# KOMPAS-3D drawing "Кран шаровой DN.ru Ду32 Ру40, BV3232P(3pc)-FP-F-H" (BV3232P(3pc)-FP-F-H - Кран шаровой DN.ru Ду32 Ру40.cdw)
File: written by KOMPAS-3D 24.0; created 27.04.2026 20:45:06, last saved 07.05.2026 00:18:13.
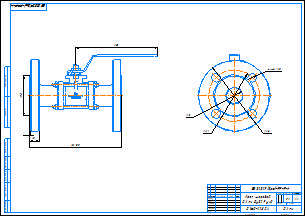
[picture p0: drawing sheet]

Document properties: Автор: Максим; Форматы листов документа: A2; Полное имя файла: BVxxP(3pc)-FP-F-H - Кран шаровой DN.ru Ду32 Ру40.cdw; Масса: 5.095; Наименование: Кран шаровой DN.ru Ду32 Ру40; Количество листов документа: 1; Примечание: D160-22804

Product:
- Body: Тело 1  | qty 1
    Масса: 4.838938
- Part/product: Кран шаровой DN.ru Ду32 Ру40  | designation BV3232P(3pc)-FP-F-H
    Масса: 5.095
    Раздел спецификации: Прочие изделия
    Форматы листов документа: A2
    Примечание: D160-22804

Views: Вид 1, Вид:2, Проекционный вид 2, Вид:1
Referenced files in D:\Rabota ebanaya\Апрель\BVxxP(3pc)-FP-F-H Кран шаровой Ду15-100\Исходники\DN32\: BVxxP(3pc)-FP-F-H - Кран шаровой DN.ru Ду32 Ру40.m3d, BVxxP(3pc)-FP-F-H - Кран шаровой DN.ru Ду32 Ру40.cdw
Referenced files in D:\Rabota ebanaya\Апрель\BV3232P(3pc)-FP-F-H Кран шаровой Ду15-100\Исходники\DN32\: BV3232P(3pc)-FP-F-H - Кран шаровой DN.ru Ду32 Ру40.m3d
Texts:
  Линейный размер
  BV3232P(3pc)-FP-F-H
  Диаметральный размер
  Кран шаровой
  DN.ru Ду32 Ру40
  Кран шаровой DN.ru Ду32 Ру40
  BV3232P(3pc)-FP-F-H Кран шаровой DN.ru Ду32 Ру40
Dimensions and other numbers on the sheet: 0; 3; 2; 4; 180±1,5; 78; 160; 18; 32; 140; 100; 4 отв.; 1:1; 1; 5,1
